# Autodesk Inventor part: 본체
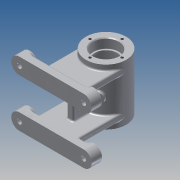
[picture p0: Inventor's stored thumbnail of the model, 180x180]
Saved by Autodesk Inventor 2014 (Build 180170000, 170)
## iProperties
Created: 2015-11
Part Number: 본체
Material: 알루미늄 6061
Document SubType Name: Modeling
Designer: 12
Density: 2.71 g/cm^3
Appearance: 알루미늄 - 평지
Mass: 358.859 g
Surface Area: 459.451 cm^2
Volume: 132.42 cm^3
Author: 12
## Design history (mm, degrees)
sketch "스케치2"
  geometry: C1 r 25 at (0, 0); 1 further point
  constraints: 1 centre point, 1 coincident
  dimensions: "d0" = 50 diameter of C1
extrude "돌출1" new body sketch "스케치2" stored distance "d1" = 70; taper "d2" = 0 deg
node "작업 평면1"
sketch "스케치5"
  geometry: L1 (-50, 30)-(50, 30); L2 (-40, 20)-(40, 20); L3 (40, 40)-(-40, 40); L4 (-82.769, 0)-(87.692, 0); L5 (40, -40)-(-40, -40); L6 (-40, -20)-(40, -20); A1 r 10 centre (-40, 30) between (-40, 40) and (-40, 20); A2 r 10 centre (40, 30) between (40, 20) and (40, 40); A3 r 10 centre (-40, -30) between (-40, -20) and (-40, -40); A4 r 10 centre (40, -30) between (40, -40) and (40, -20); 2 further points
  constraints: 14 end point, 10 point on circle, 6 symmetric about line, 4 centre point, 4 tangent, 3 point on line, 2 parallel, 1 horizontal, 1 midpoint, 1 vertical alignment, 2 other
  dimensions: "d15" = 80 distance of A2.centre A1.centre; "d16" = 40 distance from line of point (0, 0) L3; "d17" = 10 radius of A1
extrude "돌출3" join sketch "스케치5" distance "d18" = 10; taper "d19" = 0 deg
sketch "스케치6"
  geometry: L1 (25, -35)-(-25, -35) reference; L2 (-25, -35)-(-25, 35) reference; L3 (-25, 35)-(25, 35) reference; L4 (25, 35)-(25, -35) reference; L5 (-58, -40)-(-68, -40) reference; L6 (-68, -40)-(-68, -20) reference; L7 (-68, -20)-(-58, -20) reference; L8 (-58, -20)-(-58, -40) reference; L9 (-58, 20)-(-68, 20) reference; L10 (-68, 20)-(-68, 40) reference; L11 (-68, 40)-(-58, 40) reference; L12 (-58, 40)-(-58, 20) reference; L13 (-58, 20)-(0, 20); L14 (0, 20)-(0, 28); L15 (0, 28)-(-58, 28); L16 (-58, -20)-(0, -20); L17 (0, -20)-(0, -28); L18 (0, -28)-(-58, -28); 1 further point
  constraints: 12 end point, 4 perpendicular, 2 parallel, 2 point on line
  dimensions: "d20" = 8 distance of L13.end L14.end; "d21" = 58 distance of L15.end L14.end; "d22" = 8 distance of L16.end L17.end; "d23" = 58 distance of L7.end L16.end
extrude "돌출4" join sketch "스케치6" stored distance "d24" = 50; taper "d25" = 0 deg
sketch "스케치8"
  geometry: L1 (0, 20)-(-58, 20) reference; L2 (-58, -20)-(0, -20) reference; L3 (-45, 20)-(-45, -20); L4 (-4.716, 20)-(-4.716, -20); L5 (25, 35)-(-25, 35) reference; 1 further point
  constraints: 4 end point, 4 point on line, 2 perpendicular
  dimensions: "d30" = 4.71573 distance from line of L1.start L4; "d33" = 20 horizontal distance of L3.start L5.end
extrude "돌출5" join sketch "스케치8" stored distance "d31" = 8; taper "d32" = 0 deg
sketch "스케치9"
  geometry: L1 (-35, 11.5)-(-35, -11.5); L2 (-38.5, 8)-(-38.5, -8); L3 (-31.5, -8)-(-31.5, 8); L4 (-68, -20)-(-68, -40) reference; A1 r 3.5 centre (-35, 8) between (-31.5, 8) and (-38.5, 8); A2 r 3.5 centre (-35, -8) between (-38.5, -8) and (-31.5, -8); 2 further points
  constraints: 8 end point, 6 point on circle, 4 tangent, 2 centre point, 2 point on line, 1 midpoint, 1 parallel, 1 vertical
  dimensions: "d34" = 33 distance from line of L4 A2.centre; "d35" = 3.5 radius of A2; "d36" = 23 distance of L1.start L1.end; "d38" = 0 vertical distance of point (-35, 0) point (0, 0)
extrude "돌출6" cut sketch "스케치9" stored distance "d39" = 8; taper "d40" = 0 deg
node "작업 평면3"
sketch "스케치10"
  geometry: C1 r 5 at (0, 0); 1 further point
  constraints: 1 centre point, 1 coincident
  dimensions: "d41" = 10 diameter of C1
extrude "돌출7" join sketch "스케치10" distance "d42" = 3; taper "d44" = 0 deg; dims "d43" = 10, "d45" = 0
sketch "스케치13"
  geometry: L1 (-40, 40)-(40, 40) reference; L2 (40, 20)-(-40, 20) reference; C1 r 10 at (-40, -30); C2 r 10 at (40, -30); C3 r 10 at (40, 30); A1 r 10 centre (-40, -30) between (-40, -20) and (-40, -40) reference; A2 r 10 centre (40, -30) between (40, -40) and (40, -20) reference; A3 r 10 centre (40, 30) between (40, 20) and (40, 40) reference; A4 r 10 centre (-40, 30) between (-40, 40) and (-40, 20) reference; 2 further points
  constraints: 4 coincident, 3 centre point, 3 concentric, 1 vertical alignment, 2 other
extrude "돌출9" join sketch "스케치13" distance "d56" = 3; taper "d57" = 0 deg
node "작업 평면5"
sketch "스케치14"
  geometry: L1 (25, 20)-(-25, 20) reference; L2 (-25, 20)-(-25, 28) reference; L3 (-25, 28)-(25, 28) reference; L4 (25, 28)-(25, 20) reference; L5 (25, -28)-(-25, -28) reference; L6 (-25, -28)-(-25, -20) reference; L7 (-25, -20)-(25, -20) reference; L8 (25, -20)-(25, -28) reference; C1 r 10 at (40, -30) reference; C2 r 10 at (-40, -30) reference; C3 r 10 at (40, 30) reference; C4 r 10 at (-40, 30) reference; 5 further points
  constraints: 4 coincident
hole "구멍1" sketch "스케치14" at (-40, 30), (-40, -30), (40, -30), (40, 30) diameter "d59" = 6; stored, may be unused: countersink angle "d63" = 90 deg, drill point angle "d65" = 0 deg; dims "d60" = 6, "d61" = 12, "d62" = 4, "d64" = 13
sketch "스케치15"
  geometry: L1 (0, 40.643)-(0, -41.854); L2 (-38.5, 8)-(-38.5, -8) reference; L3 (-31.5, -8)-(-31.5, 8) reference; L4 (-25, 28)-(-25, 35) reference; L5 (-25, 35)-(25, 35) reference; L6 (25, 35)-(25, 5) reference; L7 (25, 5)-(28, 5) reference; L8 (28, 5)-(28, -5) reference; L9 (28, -5)-(25, -5) reference; L10 (25, -5)-(25, -35) reference; L11 (25, -35)-(-25, -35) reference; L12 (-25, -35)-(-25, -28) reference; L13 (-25, -28)-(-58, -28) reference; L14 (-58, -28)-(-58, -40) reference; L15 (-58, -40)-(-68, -40) reference; L16 (-68, -40)-(-68, -20) reference; L17 (-68, -20)-(-45, -20) reference; L18 (-45, -20)-(-45, 20) reference; L19 (-45, 20)-(-68, 20) reference; L20 (-68, 20)-(-68, 40) reference; L21 (-68, 40)-(-58, 40) reference; L22 (-58, 40)-(-58, 28) reference; L23 (-58, 28)-(-25, 28) reference; L24 (0, 35)-(16, 35); L25 (16, 35)-(16, 23); L26 (16, 23)-(14, 23); L27 (14, 23)-(14, 21); L28 (14, 21)-(21, 21); L29 (21, 21)-(21, -21); L30 (21, -21)-(14, -21); L31 (14, -21)-(14, -23); L32 (14, -23)-(16, -23); L33 (16, -23)-(16, -35); L34 (16, -35)-(0, -35); L35 (0, 35)-(0, -35); A1 r 3.5 centre (-35, 8) between (-31.5, 8) and (-38.5, 8) reference; A2 r 3.5 centre (-35, -8) between (-38.5, -8) and (-31.5, -8) reference; 1 further point
  constraints: 26 end point, 6 parallel, 3 collinear, 3 perpendicular, 3 point on line, 2 midpoint, 1 vertical
  dimensions: "d66" = 32 diameter of L24.end L1; "d67" = 28 diameter of L26.end L1; "d68" = 12 distance of L24.end L25.end; "d69" = 42 diameter of L29 L1; "d70" = 42 distance of L28.end L29.end; "d72" = 32 diameter of L33 L1; "d73" = 2 distance of L30.end L31.end
revolve "회전1" sketch "스케치15" stored, may be unused: angle "d74" = 90 deg
sketch "스케치16"
  geometry: C1 r 16 at (0, 0) reference; 4 further points
  constraints: 1 vertical alignment, 5 other
  dimensions: "d75" = 20 distance of C1.centre point (0, 20); "d78" = 360 deg dimension on C1.centre point (0, 20) (derived)
hole "구멍2" sketch "스케치16" at (0, 20), (-20, 0), (0, -20), (20, 0) diameter "d80" = 3.242; stored, may be unused: countersink angle "d84" = 90 deg, drill point angle "d86" = 118 deg; dims "d81" = 8, "d82" = 12, "d83" = 4, "d85" = 10
sketch "스케치17"
  geometry: C1 r 5 at (0, 0) reference; 1 further point
  constraints: 1 coincident
hole "구멍3" sketch "스케치17" at (0, 0) diameter "d87" = 5.188; stored, may be unused: countersink angle "d91" = 90 deg, drill point angle "d93" = 0 deg; dims "d88" = 8, "d89" = 12, "d90" = 4, "d92" = 10
sketch "스케치18"
  geometry: C1 r 5 at (0, 0) reference; 1 further point
  constraints: 1 coincident
hole "구멍4" sketch "스케치18" at (0, 0) diameter "d94" = 5.188; stored, may be unused: countersink angle "d98" = 90 deg, drill point angle "d100" = 0 deg; dims "d95" = 8, "d96" = 12, "d97" = 4, "d99" = 10
chamfer "모따기1" distance "d101" = 1; stored, may be unused: second distance "d102" = 2, angle "d103" = 45 deg
fillet "모깎기1" dims "d104" = 0.3
fillet "모깎기2" dims "d105" = 3
fillet "모깎기3" dims "d106" = 2
fillet "모깎기4" dims "d107" = 2
fillet "모깎기5" dims "d108" = 2
fillet "모깎기7" dims "d110" = 2
fillet "모깎기8" dims "d111" = 2
fillet "모깎기9" dims "d112" = 2
fillet "모깎기10" dims "d113" = 2
node "작업 평면6"
sketch "스케치19"
  geometry: L1 (-25, -35)-(-25, 35) reference; L2 (-25, -35)-(25, -35) reference; 2 further points
  constraints: 1 other
  dimensions: "d115" = 25 distance from line of L1 point (0, 0); "d116" = 35 distance from line of point (0, 0) L2
feature "엠보싱1" sketch "스케치19" dims "d0" = 50, "d117" = 0.5, "d118" = 0
fillet "모깎기11" dims "d119" = 2
fillet "모깎기12" dims "d120" = 0.3
sketch "스케치20"
  geometry: C1 r 5 at (0, 0) reference; C2 r 6 at (0, 0)
  constraints: 1 centre point, 1 coincident
  dimensions: "d121" = 12 diameter of C2
extrude "돌출10" join sketch "스케치20" distance "d122" = 5; taper "d123" = 0 deg
fillet "모깎기13" dims "d124" = 2
node "솔리드1"
pattern_circular "원형 패턴1" dims angle "d54" = 210 deg
mirror "대칭1"
node "투영된 루프1"
node "절단 모서리 투영1"
node "절단 모서리 투영3"
node "절단 모서리 투영4"
other parameters: "d3" = -68, "d58" = 3
